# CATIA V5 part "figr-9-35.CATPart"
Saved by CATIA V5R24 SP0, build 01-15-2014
Part number: Part1
Bounding box of the stored display mesh (mm): x -250 to 0, y -60 to 60, z 0 to 100
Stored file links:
  D:\KAVITA\CATIA V5-6R2014 Project_ Kavita\CATIA V5-6R2014_partfiles\Partfiles\c09_catia_v5-6r2014_prt\figr-9-35.CATPart
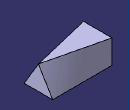
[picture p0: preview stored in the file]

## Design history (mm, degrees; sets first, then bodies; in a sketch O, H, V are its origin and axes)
Body1 (main body)
  Sketch1 on yz-plane, origin (0, 0, 0), H (0, 1, 0), V (0, 0, 1)
    point P1 (-60, 0)
    line L1 (-60, 0) -> (0, 100)
    point P2 (0, 100)
    line L2 (0, 100) -> (60, 0)
    point P3 (60, 0)
    line L3 (60, 0) -> (-60, 0)
    coincidence: P1 H, P2 V, P3 H
    horizontal: L3 H
    midpoint: O L3
  Sketch2, origin (-250, 0, 0), H (0, 1, 0), V (0, 0, 1)
    point P1 (-60, 0)
    line L1 (-60, 0) -> (60, 0)
    line L2 (60, 0) -> (60, 100)
    line L3 (60, 100) -> (-60, 100)
    line L4 (-60, 100) -> (-60, 0)
    coincidence: P1 H
    horizontal: L1 H, L3 H
    vertical: L2 V, L4 V
  Loft1: Sections (Sketch1; Sketch2), SectionCouplingPoints ({coupling CouplingPoints (vertex [element of Sketch1 | element of Sketch1]; vertex [element of Sketch2 | element of Sketch2])}; {coupling CouplingPoints (vertex [element of Sketch1 | element of Sketch1]; vertex [element of Sketch2 | element of Sketch2])}; {coupling CouplingPoints (vertex [element of Sketch1 | element of Sketch1]; vertex [element of Sketch2 | element of Sketch2])})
